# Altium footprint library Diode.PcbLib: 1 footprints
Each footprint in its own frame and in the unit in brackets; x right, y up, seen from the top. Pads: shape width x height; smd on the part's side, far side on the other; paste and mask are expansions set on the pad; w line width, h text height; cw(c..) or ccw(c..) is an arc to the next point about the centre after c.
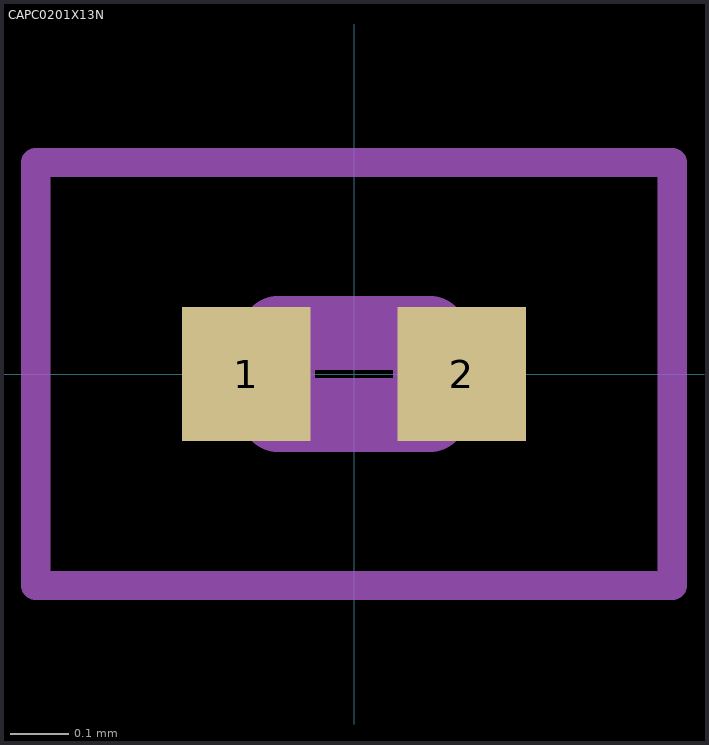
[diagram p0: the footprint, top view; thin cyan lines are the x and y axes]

## CAPC0201X13N [mm]
pads (2):
  rect 0.22x0.23 smd: 1(-0.185,0) 2(0.185,0)
Mechanical 13:
  lines w0.127: -0.13,-0.07 -0.13,0.07 0.13,0.07 0.13,-0.07 -0.13,-0.07
Mechanical 15:
  lines w0.05: -0.546,-0.363 -0.546,0.363 0.546,0.363 0.546,-0.363 -0.546,-0.363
